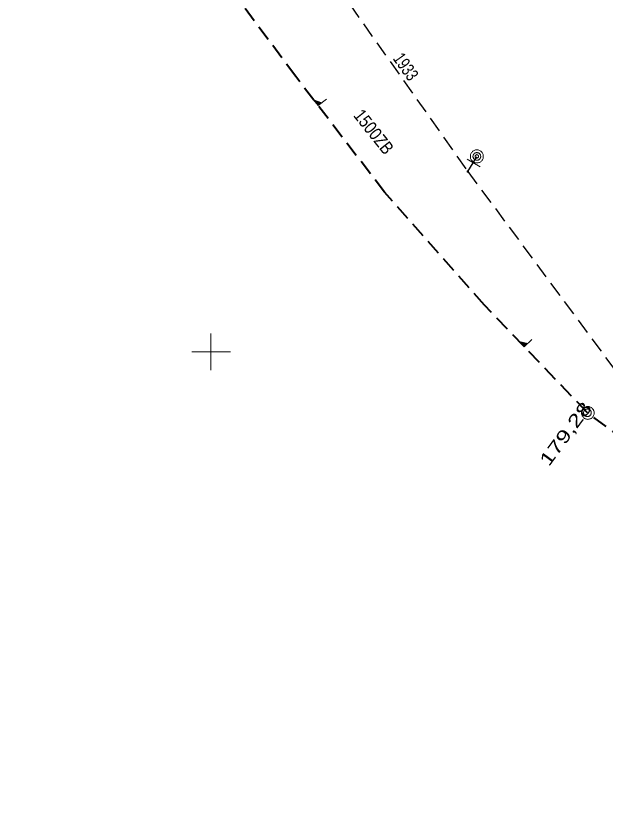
# Model space of a CAD drawing. Extents: x -740851 to -738888, y -1041382 to -1040235.
# Drawn here: x -739315.1 to -739269.3, y -1041236.1 to -1041173.9 of the extents above; entities that cross this region are included whole.
import ezdxf

# ---------------------------------------------------------------- set-up
doc = ezdxf.new("R2010")
doc.units = 0
doc.header["$LTSCALE"] = 0.4
doc.linetypes.add('MEDIUM_DASHED', pattern=[4.5, 3, -1.5])
for name, color, linetype, lineweight in [('1', 7, 'Continuous', 13), ('18', 7, 'Continuous', 13), ('8', 7, 'Continuous', 13)]:
    doc.layers.add(name, color=color, linetype=linetype, lineweight=lineweight)

msp = doc.modelspace()

# ---------------------------------------------------------------- linework, layer by layer
at = {"layer": '1'}
for p, q in [((-739300, -1041198.571), (-739300, -1041201.429)), ((-739300, -1041198.571), (-739300, -1041201.429)), ((-739301.48, -1041200), (-739298.48, -1041200)), ((-739301.48, -1041200), (-739298.48, -1041200))]:
    msp.add_line(p, q, dxfattribs=at)
at = {"layer": '18', "linetype": 'MEDIUM_DASHED', "lineweight": 40}
for points in [[(-739270.72, -1041204.75), (-739278.731, -1041196.38), (-739286.492, -1041187.581), (-739293.4, -1041178.6), (-739304.19, -1041164.07)], [(-739248.61, -1041220.28), (-739259.079, -1041213.257), (-739270.72, -1041204.75)]]:
    msp.add_lwpolyline(points, dxfattribs=at)
at = {"layer": '18'}
for points in [[(-739291.015, -1041180.361), (-739291.661, -1041180.858), (-739292.015, -1041180.397), (-739291.37, -1041180.634)], [(-739291.461, -1041180.65), (-739291.648, -1041180.794), (-739291.875, -1041180.5), (-739291.458, -1041180.653)], [(-739291.554, -1041180.668), (-739291.648, -1041180.74), (-739291.765, -1041180.589), (-739291.552, -1041180.671)], [(-739275.033, -1041199.051), (-739275.627, -1041199.62), (-739276.033, -1041199.196), (-739275.359, -1041199.363)], [(-739275.449, -1041199.389), (-739275.622, -1041199.555), (-739275.881, -1041199.284), (-739275.446, -1041199.392)], [(-739275.541, -1041199.418), (-739275.627, -1041199.501), (-739275.76, -1041199.362), (-739275.538, -1041199.421)]]:
    msp.add_lwpolyline(points, dxfattribs=at)
for points in [[(-739270.19, -1041204.76), (-739270.2, -1041204.71), (-739270.2, -1041204.66), (-739270.22, -1041204.61), (-739270.24, -1041204.56), (-739270.26, -1041204.51), (-739270.29, -1041204.47), (-739270.32, -1041204.43), (-739270.36, -1041204.39), (-739270.4, -1041204.36), (-739270.44, -1041204.33), (-739270.49, -1041204.31), (-739270.54, -1041204.29), (-739270.59, -1041204.27), (-739270.64, -1041204.27), (-739270.69, -1041204.26), (-739270.74, -1041204.27), (-739270.79, -1041204.27), (-739270.84, -1041204.29), (-739270.89, -1041204.31), (-739270.94, -1041204.33), (-739270.98, -1041204.36), (-739271.02, -1041204.39), (-739271.06, -1041204.43), (-739271.09, -1041204.47), (-739271.12, -1041204.51), (-739271.14, -1041204.56), (-739271.16, -1041204.61), (-739271.18, -1041204.66), (-739271.18, -1041204.71), (-739271.19, -1041204.76), (-739271.18, -1041204.81), (-739271.18, -1041204.86), (-739271.16, -1041204.91), (-739271.14, -1041204.96), (-739271.12, -1041205.01), (-739271.09, -1041205.05), (-739271.06, -1041205.09), (-739271.02, -1041205.13), (-739270.98, -1041205.16), (-739270.94, -1041205.19), (-739270.89, -1041205.21), (-739270.84, -1041205.23), (-739270.79, -1041205.25), (-739270.74, -1041205.25), (-739270.69, -1041205.26), (-739270.64, -1041205.25), (-739270.59, -1041205.25), (-739270.54, -1041205.23), (-739270.49, -1041205.21), (-739270.44, -1041205.19), (-739270.4, -1041205.16), (-739270.36, -1041205.13), (-739270.32, -1041205.09), (-739270.29, -1041205.05), (-739270.26, -1041205.01), (-739270.24, -1041204.96), (-739270.22, -1041204.91), (-739270.2, -1041204.86), (-739270.2, -1041204.81)], [(-739270.42, -1041204.75), (-739270.42, -1041204.72), (-739270.426, -1041204.69), (-739270.432, -1041204.66), (-739270.444, -1041204.63), (-739270.462, -1041204.6), (-739270.48, -1041204.576), (-739270.498, -1041204.552), (-739270.522, -1041204.528), (-739270.546, -1041204.51), (-739270.57, -1041204.492), (-739270.6, -1041204.474), (-739270.63, -1041204.462), (-739270.66, -1041204.456), (-739270.69, -1041204.45), (-739270.72, -1041204.45), (-739270.75, -1041204.45), (-739270.78, -1041204.456), (-739270.81, -1041204.462), (-739270.84, -1041204.474), (-739270.87, -1041204.492), (-739270.894, -1041204.51), (-739270.918, -1041204.528), (-739270.942, -1041204.552), (-739270.96, -1041204.576), (-739270.978, -1041204.6), (-739270.996, -1041204.63), (-739271.008, -1041204.66), (-739271.014, -1041204.69), (-739271.02, -1041204.72), (-739271.02, -1041204.75), (-739271.02, -1041204.78), (-739271.014, -1041204.81), (-739271.008, -1041204.84), (-739270.996, -1041204.87), (-739270.978, -1041204.9), (-739270.96, -1041204.924), (-739270.942, -1041204.948), (-739270.918, -1041204.972), (-739270.894, -1041204.99), (-739270.87, -1041205.008), (-739270.84, -1041205.026), (-739270.81, -1041205.038), (-739270.78, -1041205.044), (-739270.75, -1041205.05), (-739270.72, -1041205.05), (-739270.69, -1041205.05), (-739270.66, -1041205.044), (-739270.63, -1041205.038), (-739270.6, -1041205.026), (-739270.57, -1041205.008), (-739270.546, -1041204.99), (-739270.522, -1041204.972), (-739270.498, -1041204.948), (-739270.48, -1041204.924), (-739270.462, -1041204.9), (-739270.444, -1041204.87), (-739270.432, -1041204.84), (-739270.426, -1041204.81), (-739270.42, -1041204.78)]]:
    msp.add_lwpolyline(points, close=True, dxfattribs=at)
at = {"layer": '8', "linetype": 'MEDIUM_DASHED', "lineweight": 25}
msp.add_line((-739315.144, -1041136.272), (-739280.022, -1041185.98), dxfattribs=at)
at = {"layer": '8'}
for p, q in [((-739279.07, -1041185.627), (-739280.07, -1041185.021)), ((-739280.071, -1041186.029), (-739279.971, -1041185.929)), ((-739280.071, -1041185.929), (-739279.971, -1041186.029)), ((-739280.071, -1041185.929), (-739280.071, -1041185.949)), ((-739280.071, -1041185.929), (-739280.051, -1041185.929)), ((-739279.971, -1041185.929), (-739279.991, -1041185.929)), ((-739279.971, -1041185.929), (-739279.971, -1041185.949)), ((-739280.071, -1041186.029), (-739280.071, -1041186.009)), ((-739280.071, -1041186.029), (-739280.051, -1041186.029)), ((-739279.971, -1041186.029), (-739279.991, -1041186.029)), ((-739279.971, -1041186.029), (-739279.971, -1041186.009))]:
    msp.add_line(p, q, dxfattribs=at)
for points in [[(-739278.815, -1041184.81), (-739278.815, -1041184.764), (-739278.815, -1041184.704), (-739278.83, -1041184.658), (-739278.845, -1041184.598), (-739278.876, -1041184.552), (-739278.906, -1041184.507), (-739278.936, -1041184.476), (-739278.982, -1041184.431), (-739279.012, -1041184.401), (-739279.057, -1041184.37), (-739279.103, -1041184.34), (-739279.163, -1041184.325), (-739279.209, -1041184.31), (-739279.269, -1041184.31), (-739279.315, -1041184.31), (-739279.376, -1041184.31), (-739279.421, -1041184.31), (-739279.466, -1041184.325), (-739279.527, -1041184.34), (-739279.573, -1041184.37), (-739279.618, -1041184.401), (-739279.648, -1041184.431), (-739279.694, -1041184.476), (-739279.724, -1041184.507), (-739279.754, -1041184.552), (-739279.785, -1041184.598), (-739279.8, -1041184.658), (-739279.815, -1041184.704), (-739279.815, -1041184.764), (-739279.815, -1041184.81), (-739279.815, -1041184.87), (-739279.815, -1041184.916), (-739279.8, -1041184.961), (-739279.785, -1041185.022), (-739279.754, -1041185.067), (-739279.724, -1041185.113), (-739279.694, -1041185.143), (-739279.648, -1041185.188), (-739279.618, -1041185.219), (-739279.573, -1041185.249), (-739279.527, -1041185.279), (-739279.466, -1041185.295), (-739279.421, -1041185.31), (-739279.376, -1041185.31), (-739279.315, -1041185.31), (-739279.269, -1041185.31), (-739279.209, -1041185.31), (-739279.163, -1041185.295), (-739279.103, -1041185.279), (-739279.057, -1041185.249), (-739279.012, -1041185.219), (-739278.982, -1041185.188), (-739278.936, -1041185.143), (-739278.906, -1041185.113), (-739278.876, -1041185.067), (-739278.845, -1041185.022), (-739278.83, -1041184.961), (-739278.815, -1041184.916), (-739278.815, -1041184.87)], [(-739279.012, -1041184.81), (-739279.012, -1041184.779), (-739279.027, -1041184.749), (-739279.027, -1041184.719), (-739279.042, -1041184.688), (-739279.057, -1041184.658), (-739279.073, -1041184.628), (-739279.088, -1041184.613), (-739279.118, -1041184.582), (-739279.133, -1041184.567), (-739279.163, -1041184.552), (-739279.194, -1041184.537), (-739279.224, -1041184.522), (-739279.254, -1041184.522), (-739279.285, -1041184.507), (-739279.315, -1041184.507), (-739279.345, -1041184.507), (-739279.376, -1041184.522), (-739279.406, -1041184.522), (-739279.436, -1041184.537), (-739279.466, -1041184.552), (-739279.497, -1041184.567), (-739279.512, -1041184.582), (-739279.542, -1041184.613), (-739279.557, -1041184.628), (-739279.573, -1041184.658), (-739279.588, -1041184.688), (-739279.603, -1041184.719), (-739279.603, -1041184.749), (-739279.618, -1041184.779), (-739279.618, -1041184.81), (-739279.618, -1041184.84), (-739279.603, -1041184.87), (-739279.603, -1041184.901), (-739279.588, -1041184.931), (-739279.573, -1041184.961), (-739279.557, -1041184.992), (-739279.542, -1041185.007), (-739279.512, -1041185.037), (-739279.497, -1041185.052), (-739279.466, -1041185.067), (-739279.436, -1041185.082), (-739279.406, -1041185.098), (-739279.376, -1041185.098), (-739279.345, -1041185.113), (-739279.315, -1041185.113), (-739279.285, -1041185.113), (-739279.254, -1041185.098), (-739279.224, -1041185.098), (-739279.194, -1041185.082), (-739279.163, -1041185.067), (-739279.133, -1041185.052), (-739279.118, -1041185.037), (-739279.088, -1041185.007), (-739279.073, -1041184.992), (-739279.057, -1041184.961), (-739279.042, -1041184.931), (-739279.027, -1041184.901), (-739279.027, -1041184.87), (-739279.012, -1041184.84)], [(-739279.179, -1041184.81), (-739279.179, -1041184.795), (-739279.194, -1041184.779), (-739279.194, -1041184.764), (-739279.194, -1041184.749), (-739279.209, -1041184.749), (-739279.209, -1041184.734), (-739279.224, -1041184.719), (-739279.239, -1041184.704), (-739279.254, -1041184.704), (-739279.254, -1041184.688), (-739279.269, -1041184.688), (-739279.285, -1041184.688), (-739279.3, -1041184.673), (-739279.315, -1041184.673), (-739279.33, -1041184.673), (-739279.345, -1041184.688), (-739279.36, -1041184.688), (-739279.376, -1041184.688), (-739279.376, -1041184.704), (-739279.391, -1041184.704), (-739279.406, -1041184.719), (-739279.421, -1041184.734), (-739279.436, -1041184.749), (-739279.436, -1041184.764), (-739279.436, -1041184.779), (-739279.451, -1041184.795), (-739279.451, -1041184.81), (-739279.451, -1041184.825), (-739279.436, -1041184.84), (-739279.436, -1041184.855), (-739279.436, -1041184.87), (-739279.421, -1041184.885), (-739279.406, -1041184.901), (-739279.391, -1041184.916), (-739279.376, -1041184.931), (-739279.36, -1041184.931), (-739279.345, -1041184.931), (-739279.33, -1041184.946), (-739279.315, -1041184.946), (-739279.3, -1041184.946), (-739279.285, -1041184.931), (-739279.269, -1041184.931), (-739279.254, -1041184.931), (-739279.239, -1041184.916), (-739279.224, -1041184.901), (-739279.209, -1041184.885), (-739279.209, -1041184.87), (-739279.194, -1041184.87), (-739279.194, -1041184.855), (-739279.194, -1041184.84), (-739279.179, -1041184.825)], [(-739279.971, -1041185.979), (-739279.971, -1041185.974), (-739279.972, -1041185.969), (-739279.973, -1041185.964), (-739279.975, -1041185.959), (-739279.978, -1041185.954), (-739279.981, -1041185.95), (-739279.984, -1041185.946), (-739279.988, -1041185.942), (-739279.992, -1041185.939), (-739279.996, -1041185.936), (-739280.001, -1041185.933), (-739280.006, -1041185.931), (-739280.011, -1041185.93), (-739280.016, -1041185.929), (-739280.021, -1041185.929), (-739280.026, -1041185.929), (-739280.031, -1041185.93), (-739280.036, -1041185.931), (-739280.041, -1041185.933), (-739280.046, -1041185.936), (-739280.05, -1041185.939), (-739280.054, -1041185.942), (-739280.058, -1041185.946), (-739280.061, -1041185.95), (-739280.064, -1041185.954), (-739280.067, -1041185.959), (-739280.069, -1041185.964), (-739280.07, -1041185.969), (-739280.071, -1041185.974), (-739280.071, -1041185.979), (-739280.071, -1041185.984), (-739280.07, -1041185.989), (-739280.069, -1041185.994), (-739280.067, -1041185.999), (-739280.064, -1041186.004), (-739280.061, -1041186.008), (-739280.058, -1041186.012), (-739280.054, -1041186.016), (-739280.05, -1041186.019), (-739280.046, -1041186.022), (-739280.041, -1041186.025), (-739280.036, -1041186.027), (-739280.031, -1041186.028), (-739280.026, -1041186.029), (-739280.021, -1041186.029), (-739280.016, -1041186.029), (-739280.011, -1041186.028), (-739280.006, -1041186.027), (-739280.001, -1041186.025), (-739279.996, -1041186.022), (-739279.992, -1041186.019), (-739279.988, -1041186.016), (-739279.984, -1041186.012), (-739279.981, -1041186.008), (-739279.978, -1041186.004), (-739279.975, -1041185.999), (-739279.973, -1041185.994), (-739279.972, -1041185.989), (-739279.971, -1041185.984)]]:
    msp.add_lwpolyline(points, close=True, dxfattribs=at)
at = {"layer": '8', "lineweight": 25}
msp.add_lwpolyline([(-739280.022, -1041185.98), (-739279.61, -1041185.3), (-739279.33, -1041184.84)], dxfattribs=at)
at = {"layer": '8', "linetype": 'MEDIUM_DASHED', "lineweight": 25}
msp.add_lwpolyline([(-739280.022, -1041185.98), (-739263.345, -1041208.479), (-739258.901, -1041212.28), (-739213.353, -1041236.111)], dxfattribs=at)

# ---------------------------------------------------------------- texts
at = {"layer": '18'}
for s, rotation, width, p in [('1500ZB', 308.568, 0.85, (-739288.964, -1041181.646)), ('179,28', 53.624, 1.4, (-739273.72, -1041208.984))]:
    msp.add_text(s, height=1, rotation=rotation, dxfattribs=dict(at, width=width)).set_placement(p)
at = {"layer": '8', "width": 0.75}
msp.add_text('1933', height=1, rotation=305.244, dxfattribs=at).set_placement((-739285.885, -1041177.205))

doc.saveas('drawing.dxf')
